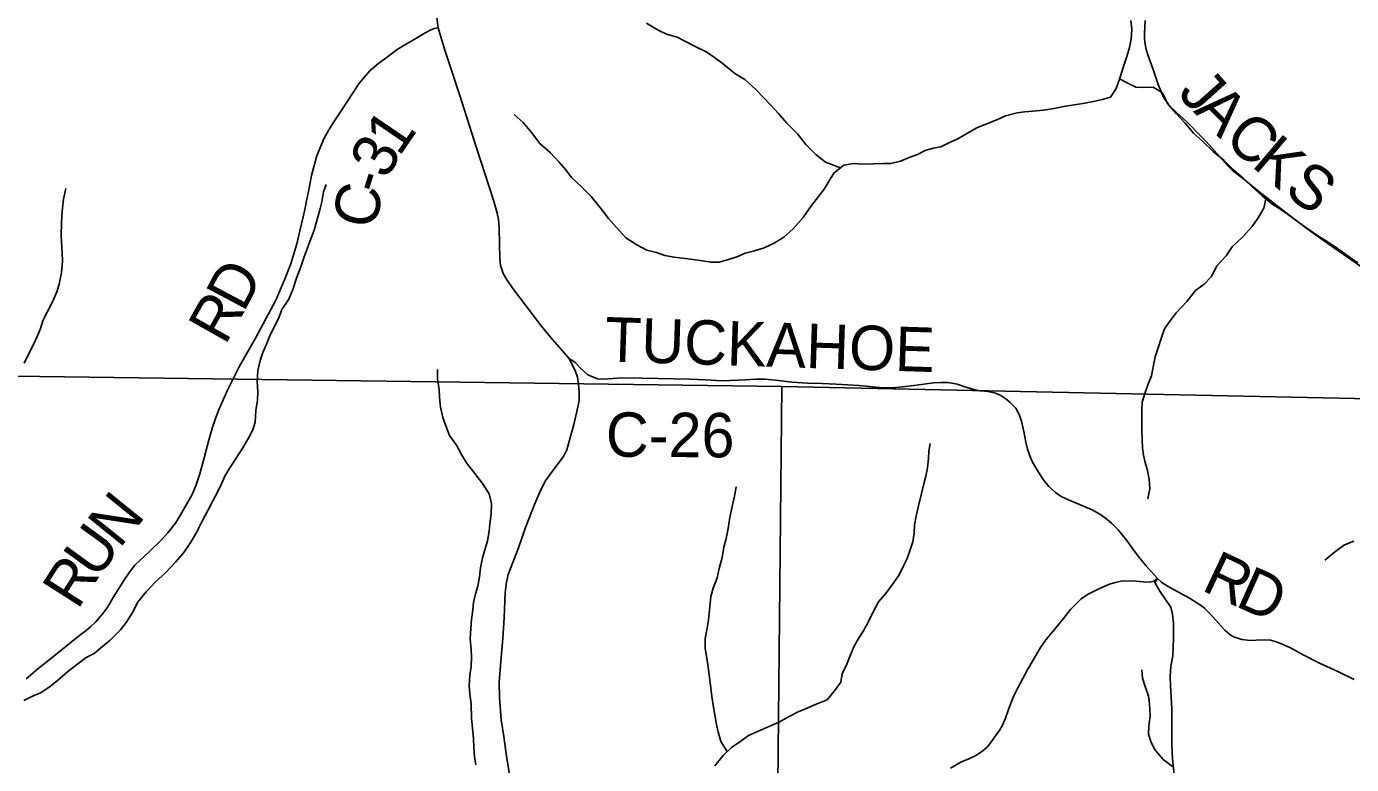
# Model space of a CAD drawing. Extents: x 0 to 191, y 0 to 55.
# Drawn here: x 187.422 to 189.118, y 52.974 to 53.918 of the extents above; entities that cross this region are included whole.
import ezdxf

# ---------------------------------------------------------------- set-up
doc = ezdxf.new("R2010")
doc.units = 0
for name, color, linetype in [('GM_X_Corporation', 7, 'Continuous'), ('GM_X_County_Road', 7, 'Continuous'), ('GM_X_County_Road_Text', 7, 'Continuous'), ('GM_X_Minor_River', 7, 'Continuous'), ('GM_X_State_Route', 7, 'Continuous'), ('GM_X_Township_Road', 7, 'Continuous'), ('GM_X_Township_Road_Text', 7, 'Continuous')]:
    doc.layers.add(name, color=color, linetype=linetype)

msp = doc.modelspace()

# ---------------------------------------------------------------- linework, layer by layer
at = {"layer": 'GM_X_Corporation'}
for points in [[(187.3751, 53.4708), (188.3886, 53.4572), (188.3785, 52.4395), (187.3608, 52.4557)], [(188.3886, 53.4572), (189.4076, 53.4357), (189.3902, 52.4217), (188.3785, 52.4395)]]:
    msp.add_lwpolyline(points, close=True, dxfattribs=at)
at = {"layer": 'GM_X_County_Road'}
for points in [[(187.949, 53.9161), (187.9436, 53.9151), (187.9388, 53.9129), (187.93, 53.9081), (187.918, 53.9011), (187.9063, 53.8942), (187.8965, 53.8881), (187.8875, 53.8815), (187.8707, 53.8692), (187.8616, 53.8609), (187.853, 53.8511), (187.8472, 53.8442), (187.8257, 53.811), (187.8161, 53.7968), (187.809, 53.7854), (187.8032, 53.7749), (187.7983, 53.7639), (187.7937, 53.7521), (187.7909, 53.7429), (187.7869, 53.727), (187.7829, 53.7067), (187.781, 53.6967), (187.7779, 53.6815), (187.772, 53.6562), (187.7679, 53.6398), (187.7603, 53.6139), (187.7524, 53.5936), (187.7412, 53.5677), (187.7149, 53.5191), (187.6946, 53.4829), (187.679, 53.4514), (187.6739, 53.4399), (187.6678, 53.4262), (187.6634, 53.4147), (187.6601, 53.4049), (187.6545, 53.3856), (187.6491, 53.3641), (187.6439, 53.3453), (187.6386, 53.33), (187.6335, 53.318), (187.6192, 53.293), (187.6128, 53.2824), (187.6029, 53.2697), (187.5945, 53.2607), (187.5799, 53.2464), (187.5608, 53.2283), (187.5537, 53.2195), (187.5465, 53.2089), (187.5401, 53.1986), (187.5331, 53.1871), (187.5259, 53.1753), (187.5216, 53.169), (187.5108, 53.1559), (187.5045, 53.1499), (187.4984, 53.145), (187.4883, 53.1371), (187.455, 53.1105), (187.4367, 53.0959), (187.4214, 53.0833)], [(188.116, 53.4932), (188.1242, 53.4878), (188.1321, 53.4799), (188.1406, 53.4719), (188.1476, 53.469), (188.1528, 53.4671), (188.1596, 53.4663), (188.1725, 53.4674), (188.1848, 53.468), (188.21, 53.4679), (188.271, 53.4663), (188.2912, 53.4658), (188.3124, 53.4645), (188.3423, 53.4657), (188.3551, 53.4664), (188.3675, 53.4663), (188.3846, 53.4649), (188.4014, 53.4628), (188.4217, 53.4614), (188.4404, 53.4608), (188.4584, 53.4601), (188.4728, 53.4591), (188.4878, 53.4582), (188.509, 53.4561), (188.5186, 53.4555), (188.53, 53.4554), (188.5437, 53.4568), (188.5576, 53.4584), (188.5705, 53.4602), (188.5831, 53.4618), (188.5927, 53.4624), (188.601, 53.4621), (188.6065, 53.4614), (188.6134, 53.4599), (188.6219, 53.4572), (188.6302, 53.4546), (188.636, 53.4529), (188.643, 53.4514), (188.6527, 53.4506), (188.6622, 53.4485), (188.6692, 53.4457), (188.6756, 53.4413), (188.6811, 53.4365), (188.6882, 53.4292), (188.6927, 53.4214), (188.6954, 53.4129), (188.6987, 53.3995), (188.701, 53.3859), (188.7032, 53.3769), (188.7062, 53.3682), (188.7093, 53.3612), (188.7125, 53.3551), (188.7172, 53.3475), (188.7232, 53.3382), (188.7305, 53.3292), (188.7391, 53.3216), (188.7464, 53.3165), (188.7557, 53.3123), (188.7861, 53.2992), (188.7956, 53.2938), (188.8049, 53.2872), (188.8112, 53.2818), (188.8192, 53.2737), (188.8302, 53.2599), (188.8375, 53.2498), (188.8461, 53.2383), (188.8546, 53.2282), (188.8614, 53.2202), (188.8694, 53.2116), (188.8746, 53.2068), (188.8803, 53.2029), (188.8861, 53.1997), (188.9104, 53.1865), (188.9247, 53.1773), (188.9296, 53.1735), (188.9345, 53.169), (188.9449, 53.1576), (188.951, 53.1505), (188.9557, 53.1454), (188.9626, 53.1393), (188.9668, 53.1368), (188.971, 53.1354), (188.9777, 53.1335), (188.9846, 53.1326), (188.9899, 53.1323), (188.9958, 53.1324), (189.0067, 53.1331), (189.0141, 53.1325), (189.0204, 53.1308), (189.0264, 53.1288), (189.039, 53.1231), (189.0559, 53.1137), (189.0769, 53.1032), (189.1004, 53.0925), (189.1212, 53.0822)]]:
    msp.add_lwpolyline(points, dxfattribs=at)
at = {"layer": 'GM_X_Minor_River'}
for points in [[(188.8356, 53.9252), (188.8367, 53.9142), (188.836, 53.9016), (188.8338, 53.891), (188.8307, 53.8807), (188.8262, 53.8663), (188.821, 53.8503), (188.8168, 53.8385), (188.8096, 53.8271), (188.7994, 53.8244), (188.7876, 53.8217), (188.7766, 53.8194), (188.766, 53.8178), (188.752, 53.8159), (188.7372, 53.8128), (188.7235, 53.8105), (188.7099, 53.8093), (188.7, 53.8085), (188.6901, 53.8073), (188.675, 53.8035), (188.664, 53.7981), (188.6522, 53.7935), (188.6382, 53.7882), (188.6284, 53.7824), (188.614, 53.774), (188.6026, 53.769), (188.5924, 53.7637), (188.5825, 53.7621), (188.5723, 53.7591), (188.5624, 53.7541), (188.5518, 53.7499), (188.5408, 53.7453), (188.5283, 53.7426), (188.5188, 53.7422), (188.5059, 53.7421), (188.4926, 53.7417), (188.4805, 53.7424), (188.468, 53.7401), (188.4555, 53.7302), (188.4494, 53.7203), (188.443, 53.7096), (188.4328, 53.6963), (188.4256, 53.6868), (188.4161, 53.6731), (188.4033, 53.6586), (188.3915, 53.6483), (188.379, 53.6406), (188.3662, 53.6345), (188.354, 53.6307), (188.3419, 53.6276), (188.3324, 53.6234), (188.3207, 53.6196), (188.3085, 53.6161), (188.2979, 53.6161), (188.2873, 53.6179), (188.2748, 53.6194), (188.2653, 53.6209), (188.2508, 53.6224), (188.2391, 53.6246), (188.2284, 53.6287), (188.2159, 53.6317), (188.2034, 53.6382), (188.1889, 53.6472), (188.1771, 53.6605), (188.1669, 53.6722), (188.1577, 53.6844), (188.1448, 53.7003), (188.1318, 53.7128), (188.1197, 53.7245), (188.1124, 53.7344), (188.1033, 53.7446), (188.0927, 53.7559), (188.079, 53.7681), (188.0683, 53.7821), (188.0576, 53.795), (188.0462, 53.8052)], [(188.4639, 53.7368), (188.4448, 53.7442), (188.4323, 53.754), (188.4197, 53.7665), (188.4087, 53.7802), (188.395, 53.7938), (188.3839, 53.8067), (188.3748, 53.8169), (188.3653, 53.8268), (188.3554, 53.837), (188.3413, 53.8499), (188.3288, 53.8574), (188.314, 53.8695), (188.3007, 53.8794), (188.2912, 53.8858), (188.2786, 53.8918), (188.2665, 53.8982), (188.2547, 53.9039), (188.241, 53.908), (188.2304, 53.9129), (188.2156, 53.922)], [(188.821, 53.8505), (188.8301, 53.8461), (188.8418, 53.8401), (188.8513, 53.8398), (188.8639, 53.8402), (188.876, 53.8326), (188.8825, 53.8193), (188.8935, 53.8065), (188.905, 53.794), (188.9156, 53.7811), (188.9274, 53.7709), (188.9411, 53.7572), (188.9548, 53.7463), (188.9673, 53.7338), (188.9791, 53.7235), (188.9909, 53.7126), (189.0035, 53.7012), (189.016, 53.6906), (189.0263, 53.6842), (189.0362, 53.6774), (189.0487, 53.6683), (189.0609, 53.6596), (189.0734, 53.6505), (189.0879, 53.6418), (189.0996, 53.6339), (189.1137, 53.624), (189.1259, 53.6153)], [(187.4191, 53.487), (187.4255, 53.5003), (187.4308, 53.5109), (187.4357, 53.5212), (187.4398, 53.5315), (187.4432, 53.5425), (187.4489, 53.5532), (187.4553, 53.5653), (187.4609, 53.5783), (187.4636, 53.5878), (187.467, 53.603), (187.4681, 53.6174), (187.4676, 53.6285), (187.4669, 53.6417), (187.4665, 53.6512), (187.4668, 53.6661), (187.4672, 53.6756), (187.4679, 53.6854), (187.4694, 53.6968), (187.4724, 53.7102)], [(187.7403, 53.5355), (187.7452, 53.5462), (187.749, 53.5557), (187.7577, 53.5687), (187.763, 53.5812), (187.7682, 53.5968), (187.7731, 53.6101), (187.7773, 53.623), (187.7811, 53.6333), (187.7848, 53.6428), (187.7901, 53.6569), (187.7931, 53.6679), (187.7976, 53.6831), (187.7999, 53.6934), (187.8021, 53.706), (187.8055, 53.7155)], [(189.0082, 53.6972), (189.0058, 53.6853), (188.9986, 53.6727), (188.9907, 53.662), (188.9786, 53.6483), (188.9653, 53.6357), (188.9574, 53.6243), (188.946, 53.6117), (188.9385, 53.5976), (188.9294, 53.5881), (188.9184, 53.5797), (188.907, 53.566), (188.8934, 53.5515), (188.8859, 53.5409), (188.8787, 53.5309), (188.8749, 53.5199), (188.87, 53.5051), (188.8666, 53.4952), (188.8644, 53.4842), (188.8618, 53.4708), (188.8572, 53.4594), (188.8538, 53.4495), (188.8501, 53.437), (188.8494, 53.4275), (188.8494, 53.4009), (188.8498, 53.3895), (188.8502, 53.3788), (188.8518, 53.3693), (188.8537, 53.3599), (188.8568, 53.3496), (188.8591, 53.3382), (188.8599, 53.326), (188.8572, 53.3135)], [(187.4186, 53.0553), (187.4289, 53.0607), (187.4399, 53.0653), (187.4509, 53.0725), (187.4611, 53.0805), (187.4751, 53.0924), (187.4876, 53.1023), (187.4982, 53.1103), (187.5084, 53.1153), (187.5194, 53.1244), (187.5292, 53.1324), (187.5425, 53.1458), (187.5497, 53.1553), (187.5584, 53.1694), (187.564, 53.1808), (187.575, 53.1945), (187.5871, 53.2071), (187.6, 53.2186), (187.6125, 53.2323), (187.6234, 53.2448), (187.6325, 53.2578), (187.6397, 53.2704), (187.6465, 53.2841), (187.654, 53.2985), (187.6601, 53.3099), (187.6665, 53.3221), (187.6714, 53.3324), (187.6759, 53.3423), (187.6824, 53.353), (187.6903, 53.3655), (187.699, 53.3785), (187.7065, 53.3918), (187.7115, 53.4017), (187.7145, 53.4116), (187.7156, 53.4264), (187.7178, 53.4397), (187.7182, 53.4504), (187.7174, 53.4633), (187.7181, 53.4777), (187.7211, 53.4903), (187.7245, 53.5005), (187.729, 53.5112), (187.7343, 53.5241), (187.7403, 53.5355)], [(187.9972, 52.9729), (187.9956, 52.9839), (187.9944, 52.9949), (187.994, 53.0067), (187.9929, 53.02), (187.9917, 53.0329), (187.9913, 53.0511), (187.9893, 53.0637), (187.9885, 53.0747), (187.9896, 53.0876), (187.9911, 53.099), (187.9915, 53.1108), (187.9911, 53.1207), (187.9899, 53.1343), (187.9906, 53.1476), (187.9917, 53.159), (187.9932, 53.1712), (187.9943, 53.1807), (187.9966, 53.1917), (187.9996, 53.2016), (188.0018, 53.2134), (188.0033, 53.2252), (188.0056, 53.2378), (188.0086, 53.248), (188.012, 53.2598), (188.0142, 53.272), (188.0149, 53.2815), (188.0168, 53.294), (188.0172, 53.307), (188.0141, 53.3199), (188.0057, 53.3328), (187.9958, 53.346), (187.9851, 53.3593), (187.979, 53.3691), (187.9722, 53.382), (187.9634, 53.3946), (187.9588, 53.4067), (187.955, 53.4173), (187.9519, 53.4306), (187.9508, 53.4435), (187.95, 53.453), (187.9481, 53.4667), (187.948, 53.4789)], [(188.303, 52.9719), (188.3136, 52.9849), (188.3242, 52.9952), (188.3363, 53.0032), (188.3462, 53.0108), (188.3606, 53.017), (188.3704, 53.0212), (188.3848, 53.0277), (188.4, 53.0357), (188.4095, 53.0407), (188.4189, 53.0445), (188.4318, 53.0503), (188.4466, 53.0564), (188.4561, 53.0678), (188.4644, 53.0789), (188.4662, 53.0895), (188.4719, 53.1017), (188.4768, 53.1139), (188.4813, 53.1249), (188.487, 53.1348), (188.4934, 53.1443), (188.4998, 53.1565), (188.5047, 53.1672), (188.5127, 53.1816), (188.521, 53.1916), (188.5293, 53.2022), (188.5388, 53.2163), (188.544, 53.2266), (188.549, 53.2369), (188.5527, 53.2468), (188.5565, 53.2582), (188.558, 53.2696), (188.5587, 53.2802), (188.5606, 53.2913), (188.5636, 53.3046), (188.5673, 53.3186), (188.5707, 53.3327), (188.573, 53.3422), (188.5752, 53.3529), (188.5767, 53.365), (188.577, 53.3745), (188.5785, 53.384)], [(188.319, 52.9901), (188.3109, 53.0028), (188.3071, 53.0153), (188.3051, 53.0248), (188.3032, 53.0369), (188.3013, 53.0464), (188.299, 53.0609), (188.2978, 53.0711), (188.2959, 53.0886), (188.2939, 53.1011), (188.2924, 53.1121), (188.2908, 53.122), (188.2908, 53.1346), (188.2931, 53.1479), (188.2949, 53.1585), (188.2968, 53.1752), (188.2979, 53.1885), (188.3009, 53.1992), (188.3058, 53.2121), (188.3084, 53.2243), (188.3122, 53.2384), (188.3144, 53.2517), (188.3174, 53.2627), (188.32, 53.2753), (188.3223, 53.2897), (188.3253, 53.3034), (188.3283, 53.3167), (188.3305, 53.3289)], [(189.1211, 53.2592), (189.109, 53.2546), (189.0961, 53.2451), (189.0836, 53.2348)], [(188.8889, 52.9708), (188.8767, 52.9799), (188.8657, 52.9931), (188.8611, 53.003), (188.858, 53.0125), (188.8584, 53.0228), (188.8603, 53.0357), (188.8595, 53.0509), (188.8583, 53.0608), (188.8541, 53.0721), (188.8506, 53.0839), (188.8495, 53.0946)]]:
    msp.add_lwpolyline(points, dxfattribs=at)
at = {"layer": 'GM_X_State_Route'}
msp.add_lwpolyline([(188.041, 52.9554), (188.0363, 52.9843), (188.033, 53.0095), (188.0295, 53.0306), (188.0273, 53.0594), (188.0271, 53.0784), (188.029, 53.1056), (188.0315, 53.1345), (188.0332, 53.161), (188.0347, 53.1935), (188.0363, 53.2066), (188.0387, 53.2165), (188.0516, 53.2506), (188.0608, 53.2766), (188.072, 53.3063), (188.0788, 53.321), (188.0859, 53.336), (188.0934, 53.3466), (188.1094, 53.3676), (188.1134, 53.376), (188.1161, 53.3853), (188.1224, 53.4086), (188.1266, 53.4253), (188.1293, 53.4393), (188.1293, 53.4496), (188.1284, 53.4605), (188.1271, 53.4692), (188.1241, 53.4774), (188.116, 53.4932), (188.0927, 53.5202), (188.0809, 53.5349), (188.0689, 53.5506), (188.0443, 53.5825), (188.0365, 53.5942), (188.0322, 53.6018), (188.0289, 53.6119), (188.0277, 53.6216), (188.0274, 53.6389), (188.0268, 53.6609), (188.026, 53.6708), (188.0245, 53.6788), (188.0201, 53.6943), (187.9978, 53.7626), (187.9762, 53.8307), (187.9626, 53.8719), (187.9574, 53.8873), (187.949, 53.9161), (187.946, 53.939)], dxfattribs=at)
at = {"layer": 'GM_X_Township_Road'}
for points in [[(189.1353, 53.6069), (189.113, 53.6224), (189.0875, 53.6401), (189.0593, 53.6602), (189.032, 53.6811), (188.9993, 53.7066), (188.9781, 53.7239), (188.9657, 53.7334), (188.9601, 53.739), (188.9458, 53.7548), (188.9318, 53.7705), (188.9256, 53.7769), (188.9076, 53.7951), (188.8936, 53.808), (188.8847, 53.8167), (188.8818, 53.8205), (188.8789, 53.8247), (188.876, 53.83), (188.8741, 53.8339), (188.8706, 53.8436), (188.8639, 53.8626), (188.8572, 53.8814), (188.8553, 53.8882), (188.8544, 53.8923), (188.8529, 53.9015), (188.853, 53.9085), (188.8537, 53.9253)], [(188.6047, 52.969), (188.618, 52.9763), (188.6281, 52.9807), (188.6363, 52.9846), (188.6419, 52.9879), (188.6464, 52.9914), (188.6516, 52.9958), (188.6563, 53.0016), (188.6633, 53.0113), (188.6674, 53.0171), (188.6713, 53.024), (188.6752, 53.0326), (188.679, 53.0439), (188.6827, 53.0542), (188.6859, 53.0614), (188.6908, 53.0715), (188.7035, 53.0953), (188.72, 53.1231), (188.7265, 53.1329), (188.7333, 53.1409), (188.7491, 53.1601), (188.7581, 53.1716), (188.7649, 53.1787), (188.772, 53.1855), (188.7799, 53.1909), (188.7944, 53.1983), (188.808, 53.204), (188.8153, 53.2065), (188.8233, 53.2082), (188.8376, 53.2083), (188.8513, 53.2071), (188.8594, 53.2067), (188.8648, 53.2082), (188.8694, 53.2116)], [(188.891, 52.9607), (188.889, 52.9809), (188.8878, 52.9985), (188.8878, 53.0209), (188.8881, 53.0324), (188.888, 53.0445), (188.8877, 53.0521), (188.8861, 53.0742), (188.8857, 53.0861), (188.8867, 53.0995), (188.8891, 53.1125), (188.89, 53.1351), (188.8901, 53.1539), (188.8887, 53.166), (188.8867, 53.1747), (188.8809, 53.1835), (188.8728, 53.1954), (188.8661, 53.2063), (188.8694, 53.2116)]]:
    msp.add_lwpolyline(points, dxfattribs=at)

# ---------------------------------------------------------------- texts
at = {"layer": 'GM_X_County_Road_Text'}
for s, height, rotation, p in [('1', 0.0568, 55.6662, (187.8989, 53.7501)), ('3', 0.0568, 61.9826, (187.8833, 53.7206)), ('-', 0.0568, 72.5426, (187.8774, 53.7009)), ('C', 0.0568, 77.8924, (187.8679, 53.6566)), ('D', 0.0568, 62.048, (187.6998, 53.5507)), ('R', 0.0568, 60.6516, (187.6762, 53.5087)), ('TUCKAHOE', 0.05682, 358.1241, (188.1617, 53.4893)), ('C-26', 0.05682, 359.6571, (188.1634, 53.3673)), ('N', 0.0568, 51.1217, (187.541, 53.2488)), ('U', 0.0568, 54.0947, (187.5121, 53.209)), ('R', 0.0568, 57.4932, (187.4875, 53.1703)), ('R', 0.0568, 334.7843, (188.9243, 53.1972)), ('D', 0.0568, 335.969, (188.9677, 53.1768))]:
    msp.add_text(s, height=height, rotation=rotation, dxfattribs=at).set_placement(p)
at = {"layer": 'GM_X_Township_Road_Text'}
for s, rotation, p in [('J', 311.7674, (188.8942, 53.8315)), ('A', 315.2962, (188.9146, 53.8088)), ('C', 318.6059, (188.9527, 53.7712)), ('K', 319.6153, (188.9886, 53.7396)), ('S', 323.4722, (189.0299, 53.7047))]:
    msp.add_text(s, height=0.0568, rotation=rotation, dxfattribs=at).set_placement(p)

doc.saveas('drawing.dxf')
